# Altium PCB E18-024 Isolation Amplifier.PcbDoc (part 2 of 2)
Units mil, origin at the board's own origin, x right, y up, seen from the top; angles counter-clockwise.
Board outline 5740 x 5970 mil, 4 copper layers (Component Side, V+, V-, Ground), stack 33.234 mil thick; 342 components, 165 nets, 939 pads, 4 vias.
Unrouted connection lines stored in the file: 473.
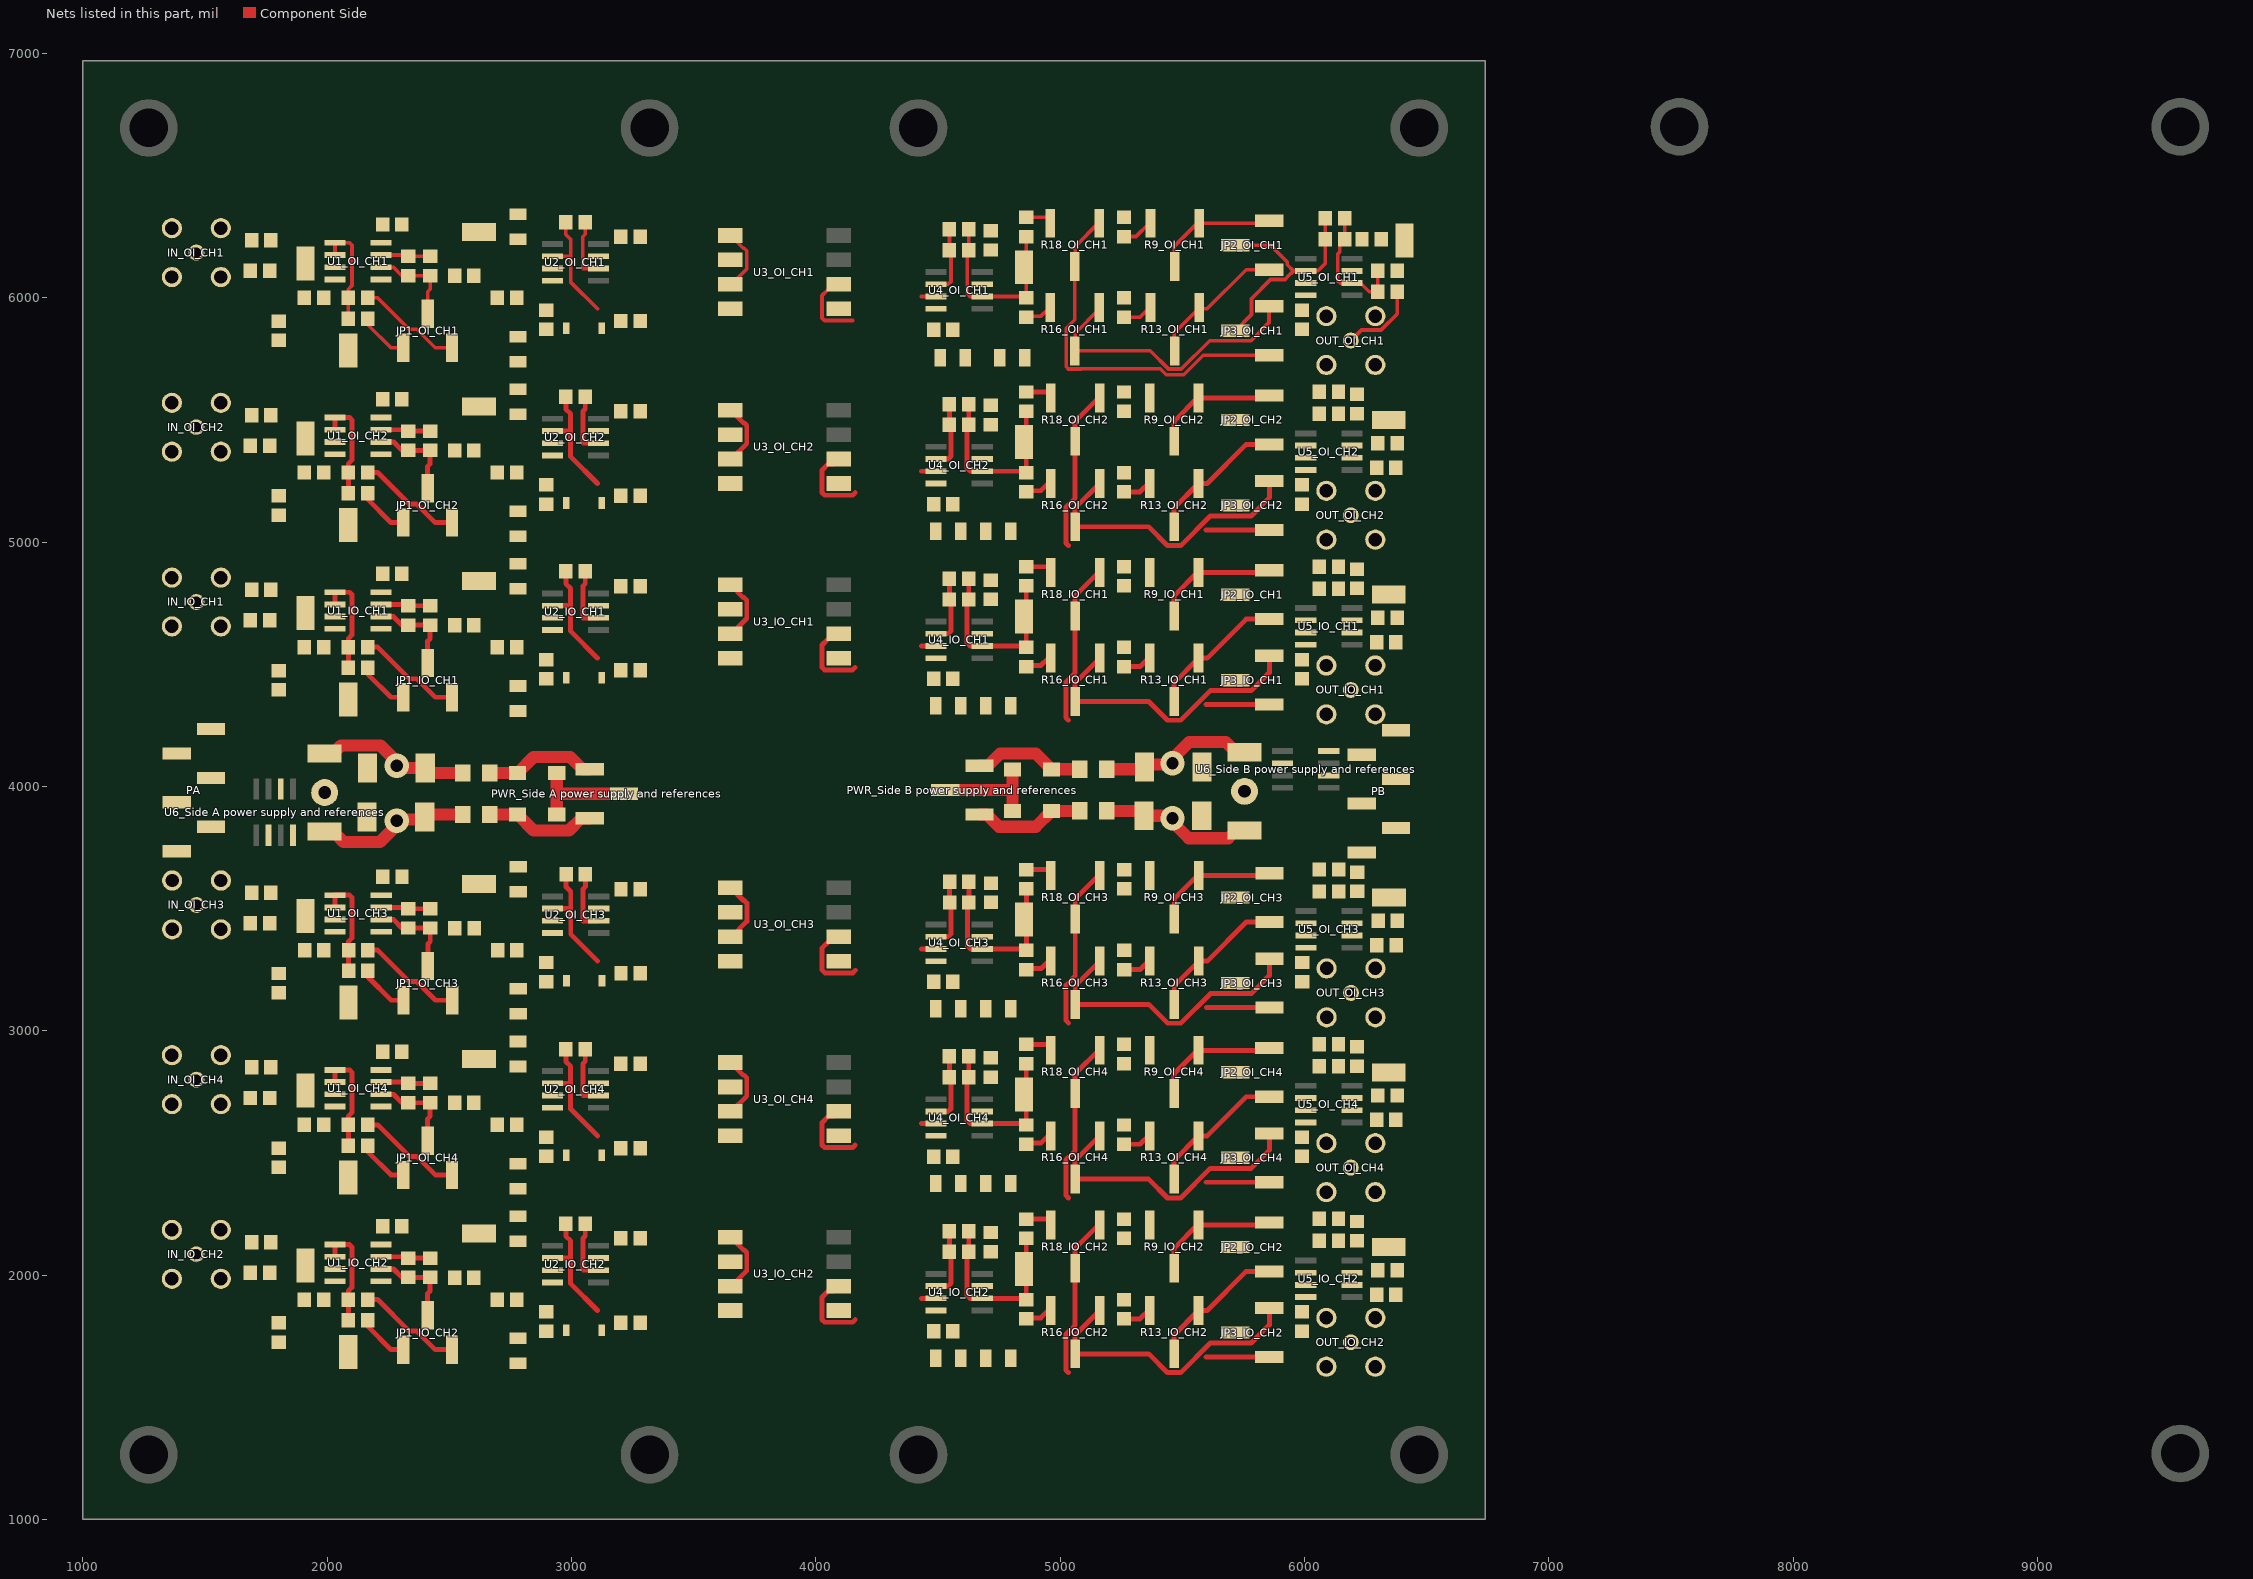
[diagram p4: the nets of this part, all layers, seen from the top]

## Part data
C1_IO_CH1 C1_IO_CH2 C1_OI_CH1 C1_OI_CH2 C1_OI_CH3 C1_OI_CH4 C2_IO_CH1 C2_IO_CH2 C2_OI_CH1 C2_OI_CH2 C2_OI_CH3 C2_OI_CH4 C3_IO_CH1 C3_IO_CH2 C3_OI_CH1 C3_OI_CH2 C3_OI_CH3 C3_OI_CH4 C4_IO_CH1 C4_IO_CH2 C4_OI_CH1 C4_OI_CH2 C4_OI_CH3 C4_OI_CH4 C6_IO_CH1 C6_IO_CH2 C6_OI_CH1 C6_OI_CH2 C6_OI_CH3 C6_OI_CH4 C7_IO_CH1 C7_IO_CH2 C7_OI_CH1 C7_OI_CH2 C7_OI_CH3 C7_OI_CH4 C8_IO_CH1 C8_IO_CH2 C8_OI_CH1 C8_OI_CH2 C8_OI_CH3 C8_OI_CH4 C9_IO_CH1 C9_IO_CH2 C9_OI_CH1 C9_OI_CH2 C9_OI_CH3 C9_OI_CH4 C14_IO_CH1 C14_IO_CH2 C14_OI_CH1 C14_OI_CH2 C14_OI_CH3 C14_OI_CH4 C15_IO_CH1 C15_IO_CH2 C15_OI_CH1 C15_OI_CH2 C15_OI_CH3 C15_OI_CH4 C16_IO_CH1 C16_IO_CH2 C16_OI_CH1 C16_OI_CH2 C16_OI_CH3 C16_OI_CH4 C17_IO_CH1 C17_IO_CH2 C17_OI_CH1 C17_OI_CH2 C17_OI_CH3 C17_OI_CH4: library part Cap, "Capacitor"
C10_IO_CH1 C10_IO_CH2 C10_OI_CH1 C10_OI_CH2 C10_OI_CH3 C10_OI_CH4 C11_IO_CH1 C11_IO_CH2 C11_OI_CH1 C11_OI_CH2 C11_OI_CH3 C11_OI_CH4 C12_IO_CH1 C12_IO_CH2 C12_OI_CH1 C12_OI_CH2 C12_OI_CH3 C12_OI_CH4 C13_IO_CH1 C13_IO_CH2 C13_OI_CH1 C13_OI_CH2 C13_OI_CH3 C13_OI_CH4: library part "Cap Pol3", "CAP TANT POLY 10UF 25V 1206"
"C18_Side A power supply and references" "C18_Side B power supply and references" "C19_Side A power supply and references" "C19_Side B power supply and references": library part "Cap Tant 100uF 10V", Manufacturer=AVX, Part Number=TCJE107M025R0080, Voltage=25V
D1_IO_CH1 D1_IO_CH2 D1_OI_CH1 D1_OI_CH2 D1_OI_CH3 D1_OI_CH4: "High Conductance Fast Diode", Manufacturer="Fairchild Semiconductor"
"D2_Side A power supply and references" "D2_Side B power supply and references" "D3_Side A power supply and references" "D3_Side B power supply and references": "Zener, 18V 1W SMAJ", Manufacturer=MCC, Part Number=SMAZ15-13-F
IN_IO_CH1 IN_IO_CH2 IN_OI_CH1 IN_OI_CH2 IN_OI_CH3 IN_OI_CH4 OUT_IO_CH1 OUT_IO_CH2 OUT_OI_CH1 OUT_OI_CH2 OUT_OI_CH3 OUT_OI_CH4: library part SMB_Male_Vertical, "SMA Male Vertical Mount", Manufacturer=Amphenol
JP1_IO_CH1 JP1_IO_CH2 JP1_OI_CH1 JP1_OI_CH2 JP1_OI_CH3 JP1_OI_CH4 JP2_IO_CH1 JP2_IO_CH2 JP2_OI_CH1 JP2_OI_CH2 JP2_OI_CH3 JP2_OI_CH4 JP3_IO_CH1 JP3_IO_CH2 JP3_OI_CH1 JP3_OI_CH2 JP3_OI_CH3 JP3_OI_CH4 "PWR_Side A power supply and references" "PWR_Side B power supply and references": library part Jumper3p, "3 Pin Jumper Header", Manufacturer="Generic Components"
PA PB: "0.1\" Spacing 1x6 Header", Manufacturer=AMP
R1_IO_CH1 R1_IO_CH2 R1_OI_CH1 R1_OI_CH2 R1_OI_CH3 R1_OI_CH4 R2_IO_CH1 R2_IO_CH2 R2_OI_CH1 R2_OI_CH2 R2_OI_CH3 R2_OI_CH4 R3_IO_CH1 R3_IO_CH2 R3_OI_CH1 R3_OI_CH2 R3_OI_CH3 R3_OI_CH4 R4_IO_CH1 R4_IO_CH2 R4_OI_CH1 R4_OI_CH2 R4_OI_CH3 R4_OI_CH4 R5_IO_CH1 R5_IO_CH2 R5_OI_CH1 R5_OI_CH2 R5_OI_CH3 R5_OI_CH4 R6_IO_CH1 R6_IO_CH2 R6_OI_CH1 R6_OI_CH2 R6_OI_CH3 R6_OI_CH4 R7_IO_CH1 R7_IO_CH2 R7_OI_CH1 R7_OI_CH2 R7_OI_CH3 R7_OI_CH4 R8_IO_CH1 R8_IO_CH2 R8_OI_CH1 R8_OI_CH2 R8_OI_CH3 R8_OI_CH4 R10_IO_CH1 R10_IO_CH2 R10_OI_CH1 R10_OI_CH2 R10_OI_CH3 R10_OI_CH4 R11_IO_CH1 R11_IO_CH2 R11_OI_CH1 R11_OI_CH2 R11_OI_CH3 R11_OI_CH4 R12_IO_CH1 R12_IO_CH2 R12_OI_CH1 R12_OI_CH2 R12_OI_CH3 R12_OI_CH4 R14_IO_CH1 R14_IO_CH2 R14_OI_CH1 R14_OI_CH2 R14_OI_CH3 R14_OI_CH4 R15_IO_CH1 R15_IO_CH2 R15_OI_CH1 R15_OI_CH2 R15_OI_CH3 R15_OI_CH4 R17_IO_CH1 R17_IO_CH2 R17_OI_CH1 R17_OI_CH2 R17_OI_CH3 R17_OI_CH4 R19_IO_CH1 R19_IO_CH2 R19_OI_CH1 R19_OI_CH2 R19_OI_CH3 R19_OI_CH4 R20_IO_CH1 R20_IO_CH2 R20_OI_CH1 R20_OI_CH2 R20_OI_CH3 R20_OI_CH4 R21_IO_CH1 R21_IO_CH2 R21_OI_CH1 R21_OI_CH2 R21_OI_CH3 R21_OI_CH4 "R27_Side A power supply and references" "R27_Side B power supply and references" "R28_Side A power supply and references" "R28_Side B power supply and references": library part Res1, "Resistor"
R9_IO_CH1 R9_IO_CH2 R9_OI_CH1 R9_OI_CH2 R9_OI_CH3 R9_OI_CH4 R13_IO_CH1 R13_IO_CH2 R13_OI_CH1 R13_OI_CH2 R13_OI_CH3 R13_OI_CH4 R16_IO_CH1 R16_IO_CH2 R16_OI_CH1 R16_OI_CH2 R16_OI_CH3 R16_OI_CH4 R18_IO_CH1 R18_IO_CH2 R18_OI_CH1 R18_OI_CH2 R18_OI_CH3 R18_OI_CH4: "SMD POT", Manufacturer=Vishay, Part Number=TS63Y
TP1_IO_CH1 TP1_IO_CH2 TP1_OI_CH1 TP1_OI_CH2 TP1_OI_CH3 TP1_OI_CH4 TP2_IO_CH1 TP2_IO_CH2 TP2_OI_CH1 TP2_OI_CH2 TP2_OI_CH3 TP2_OI_CH4 TP3_IO_CH1 TP3_IO_CH2 TP3_OI_CH1 TP3_OI_CH2 TP3_OI_CH3 TP3_OI_CH4 TP4_IO_CH1 TP4_IO_CH2 TP4_OI_CH1 TP4_OI_CH2 TP4_OI_CH3 TP4_OI_CH4 TP5_IO_CH1 TP5_IO_CH2 TP5_OI_CH1 TP5_OI_CH2 TP5_OI_CH3 TP5_OI_CH4 "TP+_Side A power supply and references" "TP+_Side B power supply and references" "TP-_Side A power supply and references" "TP-_Side B power supply and references" "TPCOM_Side A power supply and references" "TPCOM_Side B power supply and references": library part "TP- Eyelet Terminal", "Eyelet Test Point (white)", Manufacturer=Vero, Part Number=20-313143A
U1_IO_CH1 U1_IO_CH2 U1_OI_CH1 U1_OI_CH2 U1_OI_CH3 U1_OI_CH4 U5_IO_CH1 U5_IO_CH2 U5_OI_CH1 U5_OI_CH2 U5_OI_CH3 U5_OI_CH4: "OVP and EMI Protected, Precision, / Low Noise and Bias Current Dual Op Amp", Manufacturer="Analog Devices"
U2_IO_CH1 U2_IO_CH2 U2_OI_CH1 U2_OI_CH2 U2_OI_CH3 U2_OI_CH4: "36V, 18MHz, Low Noise, JFET Op Amp", Manufacturer="Analog Devices"
U3_IO_CH1 U3_IO_CH2 U3_OI_CH1 U3_OI_CH2 U3_OI_CH3 U3_OI_CH4: "Analog Optocoupler", Manufacturer=Agilent
U4_IO_CH1 U4_IO_CH2 U4_OI_CH1 U4_OI_CH2 U4_OI_CH3 U4_OI_CH4: "36V, 18MHz, Low Noise, JFET Op Amp", Manufacturer="Analog Devices", Part Number=AD548KR
"U6_Side A power supply and references" "U6_Side B power supply and references": "2ppm/°C, Low-Noise, +10V Voltage Reference", Manufacturer=Maxim, Part Number=MAX6325CSA

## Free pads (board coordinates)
  round 236.22 hole 157.48: 5(1270,1265) 5(1270,6695) 5(3320,1265) 5(3320,6695) 5(4420,1265) 5(4420,6695) 5(6470,1265) 5(6470,6695) 5(7535,6700) 5(9585,1270) 5(9585,6700)

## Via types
v1: diameter 100, hole 50, Component Side to Ground, tented both sides, 4 vias

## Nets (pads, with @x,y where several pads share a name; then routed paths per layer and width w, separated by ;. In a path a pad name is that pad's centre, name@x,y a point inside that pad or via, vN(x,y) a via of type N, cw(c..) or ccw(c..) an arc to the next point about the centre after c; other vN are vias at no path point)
+10REFA: "U6_Side A power supply and references.6" R1_IO_CH1.2 R1_IO_CH2.2 R8_OI_CH1.2 R8_OI_CH2.2 R8_OI_CH3.2 R8_OI_CH4.2 R11_OI_CH1.2 R11_OI_CH2.2 R11_OI_CH3.2 R11_OI_CH4.2
+10REFB: "U6_Side B power supply and references.6" R1_OI_CH1.2 R1_OI_CH2.2 R1_OI_CH3.2 R1_OI_CH4.2 R8_IO_CH1.2 R8_IO_CH2.2 R11_IO_CH1.2 R11_IO_CH2.2
+15A: "C18_Side A power supply and references.1" "R27_Side A power supply and references.1" "TP+_Side A power supply and references.1" "U6_Side A power supply and references.2" C6_IO_CH1.2 C6_IO_CH2.2 C7_IO_CH1.2 C7_IO_CH2.2 C8_OI_CH1.2 C8_OI_CH2.2 C8_OI_CH3.2 C8_OI_CH4.2 C9_OI_CH1.2 C9_OI_CH2.2 C9_OI_CH3.2 C9_OI_CH4.2 C10_IO_CH1.1 C10_IO_CH2.1 C11_OI_CH1.1 C11_OI_CH2.1 C11_OI_CH3.1 C11_OI_CH4.1 U1_IO_CH1.8 U1_IO_CH2.8 U2_IO_CH1.7 U2_IO_CH2.7 U4_OI_CH1.7 U4_OI_CH2.7 U4_OI_CH3.7 U4_OI_CH4.7 U5_OI_CH1.7 U5_OI_CH2.7 U5_OI_CH3.7 U5_OI_CH4.7 | length 609.6
  Component Side w20: 1960,3815 1990,3815
  Component Side w50: 2035,3805 2067.06,3772.94 2216.82,3772.94 2308.87,3865 2400,3865 2420,3885 2554.88,3885
  other v1: 2285,3860
+15B: "C18_Side B power supply and references.1" "R27_Side B power supply and references.1" "TP+_Side B power supply and references.1" "U6_Side B power supply and references.2" C6_OI_CH1.2 C6_OI_CH2.2 C6_OI_CH3.2 C6_OI_CH4.2 C7_OI_CH1.2 C7_OI_CH2.2 C7_OI_CH3.2 C7_OI_CH4.2 C8_IO_CH2.2 C9_IO_CH2.2 C10_OI_CH1.1 C10_OI_CH2.1 C10_OI_CH3.1 C10_OI_CH4.1 C11_IO_CH2.1 U1_OI_CH1.8 U1_OI_CH2.8 U1_OI_CH3.8 U1_OI_CH4.8 U2_OI_CH1.7 U2_OI_CH2.7 U2_OI_CH3.7 U2_OI_CH4.7 U4_IO_CH2.7 U5_IO_CH2.7 | length 609.6
  Component Side w20: 5755,4140 5785,4140
  Component Side w50: 5190.12,4070 5325,4070 5345,4090 5436.13,4090 5528.18,4182.06 5677.94,4182.06 5710,4150
  other v1: 5460,4095
"+Vin_Side A power supply and references": "D2_Side A power supply and references.2" "PWR_Side A power supply and references.1" "R27_Side A power supply and references.2" | length 457.6
  Component Side w50: 2665,3885 2665.12,3885 2780,3885 2845,3820 2990,3820 3040,3870 3075,3870
"+Vin_Side B power supply and references": "D2_Side B power supply and references.2" "PWR_Side B power supply and references.1" "R27_Side B power supply and references.2" | length 457.6
  Component Side w50: 4670,4085 4705,4085 4755,4135 4900,4135 4965,4070 5079.88,4070 5080,4070
-15A: "C19_Side A power supply and references.2" "R28_Side A power supply and references.1" "TP-_Side A power supply and references.1" C12_IO_CH1.2 C12_IO_CH2.2 C13_OI_CH1.2 C13_OI_CH2.2 C13_OI_CH3.2 C13_OI_CH4.2 C14_IO_CH1.2 C14_IO_CH2.2 C15_IO_CH1.2 C15_IO_CH2.2 C16_OI_CH1.2 C16_OI_CH2.2 C16_OI_CH3.2 C16_OI_CH4.2 C17_OI_CH1.2 C17_OI_CH2.2 C17_OI_CH3.2 C17_OI_CH4.2 U1_IO_CH1.4 U1_IO_CH2.4 U2_IO_CH1.4 U2_IO_CH2.4 U4_OI_CH1.4 U4_OI_CH2.4 U4_OI_CH3.4 U4_OI_CH4.4 U5_OI_CH1.4 U5_OI_CH2.4 U5_OI_CH3.4 U5_OI_CH4.4 | length 592.9
  Component Side w50: 2025,4135 2057.06,4167.06 2218.04,4167.06 2310.09,4075 2401.22,4075 ; 2400,4080 2425,4055 2554.88,4055
  other v1: 2285,4085
-15B: "C19_Side B power supply and references.2" "R28_Side B power supply and references.1" "TP-_Side B power supply and references.1" C12_OI_CH1.2 C12_OI_CH2.2 C12_OI_CH3.2 C12_OI_CH4.2 C13_IO_CH2.2 C14_OI_CH1.2 C14_OI_CH2.2 C14_OI_CH3.2 C14_OI_CH4.2 C15_OI_CH1.2 C15_OI_CH2.2 C15_OI_CH3.2 C15_OI_CH4.2 C16_IO_CH2.2 C17_IO_CH2.2 U1_OI_CH1.4 U1_OI_CH2.4 U1_OI_CH3.4 U1_OI_CH4.4 U2_OI_CH1.4 U2_OI_CH2.4 U2_OI_CH3.4 U2_OI_CH4.4 U4_IO_CH2.4 U5_IO_CH2.4 | length 592.9
  Component Side w50: 5190.12,3900 5320,3900 5345,3875 ; 5343.78,3880 5434.91,3880 5526.96,3787.94 5687.94,3787.94 5720,3820
  other v1: 5460,3870
"-Vin_Side A power supply and references": "D3_Side A power supply and references.1" "PWR_Side A power supply and references.3" "R28_Side A power supply and references.2" | length 457.6
  Component Side w50: 2665,4055 2665.12,4055 2780,4055 2845,4120 2995,4120 3045,4070 3075,4070
"-Vin_Side B power supply and references": "D3_Side B power supply and references.1" "PWR_Side B power supply and references.3" "R28_Side B power supply and references.2" | length 457.6
  Component Side w50: 4670,3885 4700,3885 4750,3835 4900,3835 4965,3900 5079.88,3900 5080,3900
COMA: "C18_Side A power supply and references.2" "C19_Side A power supply and references.1" "D2_Side A power supply and references.1" "D3_Side A power supply and references.2" "PWR_Side A power supply and references.2" "TPCOM_Side A power supply and references.1" "U6_Side A power supply and references.4" C6_IO_CH1.1 C6_IO_CH2.1 C7_IO_CH1.1 C7_IO_CH2.1 C8_OI_CH1.1 C8_OI_CH2.1 C8_OI_CH3.1 C8_OI_CH4.1 C9_OI_CH1.1 C9_OI_CH2.1 C9_OI_CH3.1 C9_OI_CH4.1 C10_IO_CH1.2 C10_IO_CH2.2 C11_OI_CH1.2 C11_OI_CH2.2 C11_OI_CH3.2 C11_OI_CH4.2 C12_IO_CH1.1 C12_IO_CH2.1 C13_OI_CH1.1 C13_OI_CH2.1 C13_OI_CH3.1 C13_OI_CH4.1 C14_IO_CH1.1 C14_IO_CH2.1 C15_IO_CH1.1 C15_IO_CH2.1 C16_OI_CH1.1 C16_OI_CH2.1 C16_OI_CH3.1 C16_OI_CH4.1 C17_OI_CH1.1 C17_OI_CH2.1 C17_OI_CH3.1 C17_OI_CH4.1 D1_IO_CH1.1 D1_IO_CH2.1 IN_IO_CH1.2 IN_IO_CH2.2 OUT_OI_CH1.2 OUT_OI_CH2.2 OUT_OI_CH3.2 OUT_OI_CH4.2 R7_IO_CH1.1 R7_IO_CH2.1 U1_IO_CH1.5 U1_IO_CH2.5 U2_IO_CH1.3 U2_IO_CH2.3 U3_IO_CH1.1 U3_IO_CH1.3 U3_IO_CH2.1 U3_IO_CH2.3 U3_OI_CH1.6 U3_OI_CH2.6 U3_OI_CH3.6 U3_OI_CH4.6 U4_OI_CH1.3 U4_OI_CH2.3 U4_OI_CH3.3 U4_OI_CH4.3 U5_OI_CH1.3 U5_OI_CH2.3 U5_OI_CH3.3 U5_OI_CH4.3 | length 2484.5
  Component Side w15: U3_OI_CH1.6@4093.54,6055 4073.54,6035 4051.54,6035 4025.54,6009 4025.54,5917.54 4036.08,5907 4150.99,5907 ; 4431.54,6005 U4_OI_CH1.3@4491.54,6005
  Component Side w20: U3_IO_CH2.3@3649.54,1955 3654.99,1955 3717.54,2017.54 3717.54,2092.46 3706.99,2103 3703.54,2103 U3_IO_CH2.1@3651.54,2155 ; U3_IO_CH1.3@3649.54,4625 3654.99,4625 3717.54,4687.54 3717.54,4762.46 3706.99,4773 3703.54,4773 U3_IO_CH1.1@3651.54,4825 ; U3_OI_CH4.6@4093.54,2670 4073.54,2650 4051.54,2650 4025.54,2624 4025.54,2532.54 4036.08,2522 4150.99,2522 4161.54,2532.54 ; U3_OI_CH2.6@4093.54,5340 4073.54,5320 4051.54,5320 4025.54,5294 4025.54,5202.54 4036.08,5192 4150.99,5192 4161.54,5202.54 ; U3_OI_CH3.6@4094.17,3385 4074.17,3365 4052.17,3365 4026.17,3339 4026.17,3247.54 4036.71,3237 4151.62,3237 4162.17,3247.54 ; 4431.54,2620 U4_OI_CH4.3@4491.54,2620 ; 4431.54,5290 U4_OI_CH2.3@4491.54,5290 ; 4432.17,3335 U4_OI_CH3.3@4492.17,3335
  Component Side w50: 2940,3885 2940,3970 ; 2940,4055 2940,3970 ; 3215,3970 2940,3970
COMB: "C18_Side B power supply and references.2" "C19_Side B power supply and references.1" "D2_Side B power supply and references.1" "D3_Side B power supply and references.2" "PWR_Side B power supply and references.2" "TPCOM_Side B power supply and references.1" "U6_Side B power supply and references.4" C6_OI_CH1.1 C6_OI_CH2.1 C6_OI_CH3.1 C6_OI_CH4.1 C7_OI_CH1.1 C7_OI_CH2.1 C7_OI_CH3.1 C7_OI_CH4.1 C8_IO_CH2.1 C9_IO_CH2.1 C10_OI_CH1.2 C10_OI_CH2.2 C10_OI_CH3.2 C10_OI_CH4.2 C11_IO_CH2.2 C12_OI_CH1.1 C12_OI_CH2.1 C12_OI_CH3.1 C12_OI_CH4.1 C13_IO_CH2.1 C14_OI_CH1.1 C14_OI_CH2.1 C14_OI_CH3.1 C14_OI_CH4.1 C15_OI_CH1.1 C15_OI_CH2.1 C15_OI_CH3.1 C15_OI_CH4.1 C16_IO_CH2.1 C17_IO_CH2.1 D1_OI_CH1.1 D1_OI_CH2.1 D1_OI_CH3.1 D1_OI_CH4.1 IN_OI_CH1.2 IN_OI_CH2.2 IN_OI_CH3.2 IN_OI_CH4.2 OUT_IO_CH2.2 R7_OI_CH1.1 R7_OI_CH2.1 R7_OI_CH3.1 R7_OI_CH4.1 U1_OI_CH1.5 U1_OI_CH2.5 U1_OI_CH3.5 U1_OI_CH4.5 U2_OI_CH1.3 U2_OI_CH2.3 U2_OI_CH3.3 U2_OI_CH4.3 U3_IO_CH2.6 U3_OI_CH1.1 U3_OI_CH1.3 U3_OI_CH2.1 U3_OI_CH2.3 U3_OI_CH3.1 U3_OI_CH3.3 U3_OI_CH4.1 U3_OI_CH4.3 U4_IO_CH2.3 U5_IO_CH2.3 | length 1871.1
  Component Side w15: U3_OI_CH1.3@3649.54,6055 3654.99,6055 3717.54,6117.54 3717.54,6192.46 3706.99,6203 3703.54,6203 U3_OI_CH1.1@3651.54,6255
  Component Side w20: U3_OI_CH4.3@3649.54,2670 3654.99,2670 3717.54,2732.54 3717.54,2807.46 3706.99,2818 3703.54,2818 U3_OI_CH4.1@3651.54,2870 ; U3_OI_CH2.3@3649.54,5340 3654.99,5340 3717.54,5402.54 3717.54,5477.46 3706.99,5488 3703.54,5488 U3_OI_CH2.1@3651.54,5540 ; U3_OI_CH3.3@3650.17,3385 3655.62,3385 3718.17,3447.54 3718.17,3522.46 3707.62,3533 3704.17,3533 U3_OI_CH3.1@3652.17,3585 ; U3_IO_CH2.6@4093.54,1955 4073.54,1935 4051.54,1935 4025.54,1909 4025.54,1817.54 4036.08,1807 4150.99,1807 4161.54,1817.54 ; 4431.54,1905 U4_IO_CH2.3@4491.54,1905
  Component Side w50: 4530,3985 4805,3985 ; 4805,3900 4805,3985 ; 4805,4070 4805,3985
COMOUT_IO_CH1: C8_IO_CH1.1 C9_IO_CH1.1 C11_IO_CH1.2 C13_IO_CH1.1 C16_IO_CH1.1 C17_IO_CH1.1 OUT_IO_CH1.2 U3_IO_CH1.6 U4_IO_CH1.3 U5_IO_CH1.3 | length 383.2
  Component Side w20: U3_IO_CH1.6@4093.54,4625 4073.54,4605 4051.54,4605 4025.54,4579 4025.54,4487.54 4036.08,4477 4150.99,4477 4161.54,4487.54 ; 4431.54,4575 U4_IO_CH1.3@4491.54,4575
NetC1_IO_CH1_1: C1_IO_CH1.1 R2_IO_CH1.1 R4_IO_CH1.1 TP3_IO_CH1.1 U1_IO_CH1.7 | length 207.8
  Component Side w20: U1_IO_CH1.7@2221.02,4745 2331.54,4745 R2_IO_CH1.1@2336.54,4740 ; R2_IO_CH1.1@2331.54,4740 R2_IO_CH1.1@2332.17,4739.37 C1_IO_CH1.1@2421.54,4739.37
NetC1_IO_CH1_2: C1_IO_CH1.2 JP1_IO_CH1.2 R1_IO_CH1.1 R2_IO_CH1.2 U1_IO_CH1.6 | length 368.6
  Component Side w20: U1_IO_CH1.6@2226.54,4695 2271.54,4695 2305.91,4660.63 R2_IO_CH1.2@2332.17,4660.63 2420.91,4660.63 2421.54,4660 2421.54,4605 2411.54,4595 JP1_IO_CH1.2@2411.54,4505
NetC1_IO_CH2_1: C1_IO_CH2.1 R2_IO_CH2.1 R4_IO_CH2.1 TP3_IO_CH2.1 U1_IO_CH2.7 | length 207.8
  Component Side w20: U1_IO_CH2.7@2221.02,2075 2331.54,2075 R2_IO_CH2.1@2336.54,2070 ; R2_IO_CH2.1@2331.54,2070 R2_IO_CH2.1@2332.17,2069.37 C1_IO_CH2.1@2421.54,2069.37
NetC1_IO_CH2_2: C1_IO_CH2.2 JP1_IO_CH2.2 R1_IO_CH2.1 R2_IO_CH2.2 U1_IO_CH2.6 | length 368.6
  Component Side w20: U1_IO_CH2.6@2226.54,2025 2271.54,2025 2305.91,1990.63 R2_IO_CH2.2@2332.17,1990.63 2420.91,1990.63 2421.54,1990 2421.54,1935 2411.54,1925 JP1_IO_CH2.2@2411.54,1835
NetC1_OI_CH1_1: C1_OI_CH1.1 R2_OI_CH1.1 R4_OI_CH1.1 TP3_OI_CH1.1 U1_OI_CH1.7 | length 207.8
  Component Side w15: U1_OI_CH1.7@2221.02,6175 2331.54,6175 R2_OI_CH1.1@2336.54,6170 ; R2_OI_CH1.1@2331.54,6170 R2_OI_CH1.1@2332.17,6169.37 C1_OI_CH1.1@2421.54,6169.37
NetC1_OI_CH1_2: C1_OI_CH1.2 JP1_OI_CH1.2 R1_OI_CH1.1 R2_OI_CH1.2 U1_OI_CH1.6 | length 368.6
  Component Side w15: U1_OI_CH1.6@2226.54,6125 2271.54,6125 2305.91,6090.63 R2_OI_CH1.2@2332.17,6090.63 2420.91,6090.63 2421.54,6090 2421.54,6035 2411.54,6025 JP1_OI_CH1.2@2411.54,5935
NetC1_OI_CH2_1: C1_OI_CH2.1 R2_OI_CH2.1 R4_OI_CH2.1 TP3_OI_CH2.1 U1_OI_CH2.7 | length 207.8
  Component Side w20: U1_OI_CH2.7@2221.02,5460 2331.54,5460 R2_OI_CH2.1@2336.54,5455 ; R2_OI_CH2.1@2331.54,5455 R2_OI_CH2.1@2332.17,5454.37 C1_OI_CH2.1@2421.54,5454.37
NetC1_OI_CH2_2: C1_OI_CH2.2 JP1_OI_CH2.2 R1_OI_CH2.1 R2_OI_CH2.2 U1_OI_CH2.6 | length 368.6
  Component Side w20: U1_OI_CH2.6@2226.54,5410 2271.54,5410 2305.91,5375.63 R2_OI_CH2.2@2332.17,5375.63 2420.91,5375.63 2421.54,5375 2421.54,5320 2411.54,5310 JP1_OI_CH2.2@2411.54,5220
NetC1_OI_CH3_1: C1_OI_CH3.1 R2_OI_CH3.1 R4_OI_CH3.1 TP3_OI_CH3.1 U1_OI_CH3.7 | length 207.8
  Component Side w20: U1_OI_CH3.7@2221.65,3505 2332.17,3505 R2_OI_CH3.1@2337.17,3500 ; R2_OI_CH3.1@2332.17,3500 R2_OI_CH3.1@2332.8,3499.37 C1_OI_CH3.1@2422.17,3499.37
NetC1_OI_CH3_2: C1_OI_CH3.2 JP1_OI_CH3.2 R1_OI_CH3.1 R2_OI_CH3.2 U1_OI_CH3.6 | length 368.6
  Component Side w20: U1_OI_CH3.6@2227.17,3455 2272.17,3455 2306.54,3420.63 R2_OI_CH3.2@2332.8,3420.63 2421.54,3420.63 2422.17,3420 2422.17,3365 2412.17,3355 JP1_OI_CH3.2@2412.17,3265
NetC1_OI_CH4_1: C1_OI_CH4.1 R2_OI_CH4.1 R4_OI_CH4.1 TP3_OI_CH4.1 U1_OI_CH4.7 | length 207.8
  Component Side w20: U1_OI_CH4.7@2221.02,2790 2331.54,2790 R2_OI_CH4.1@2336.54,2785 ; R2_OI_CH4.1@2331.54,2785 R2_OI_CH4.1@2332.17,2784.37 C1_OI_CH4.1@2421.54,2784.37
NetC1_OI_CH4_2: C1_OI_CH4.2 JP1_OI_CH4.2 R1_OI_CH4.1 R2_OI_CH4.2 U1_OI_CH4.6 | length 368.6
  Component Side w20: U1_OI_CH4.6@2226.54,2740 2271.54,2740 2305.91,2705.63 R2_OI_CH4.2@2332.17,2705.63 2420.91,2705.63 2421.54,2705 2421.54,2650 2411.54,2640 JP1_OI_CH4.2@2411.54,2550
NetC2_IO_CH1_1: C2_IO_CH1.1 R5_IO_CH1.1 U2_IO_CH1.6 | length 248.6
  Component Side w20: C2_IO_CH1.1@3056.54,4870 3056.54,4830 3046.54,4820 3046.54,4690 U2_IO_CH1.6@3111.02,4690
NetC2_IO_CH1_2: C2_IO_CH1.2 R4_IO_CH1.2 U2_IO_CH1.2 U3_IO_CH1.4 | length 475.6
  Component Side w20: U2_IO_CH1.2@2921.54,4740 U2_IO_CH1.2@2922.05,4740 2996.54,4740 ; C2_IO_CH1.2@2977.17,4870 2977.17,4829.37 2996.54,4810 2996.54,4740 ; 3106.54,4525 2996.54,4635 2996.54,4740 ; U3_IO_CH1.4@3649.54,4525 U3_IO_CH1.4@3651.54,4525
NetC2_IO_CH2_1: C2_IO_CH2.1 R5_IO_CH2.1 U2_IO_CH2.6 | length 248.6
  Component Side w20: C2_IO_CH2.1@3056.54,2200 3056.54,2160 3046.54,2150 3046.54,2020 U2_IO_CH2.6@3111.02,2020
NetC2_IO_CH2_2: C2_IO_CH2.2 R4_IO_CH2.2 U2_IO_CH2.2 U3_IO_CH2.4 | length 475.6
  Component Side w20: U2_IO_CH2.2@2921.54,2070 U2_IO_CH2.2@2922.05,2070 2996.54,2070 ; C2_IO_CH2.2@2977.17,2200 2977.17,2159.37 2996.54,2140 2996.54,2070 ; 3106.54,1855 2996.54,1965 2996.54,2070 ; U3_IO_CH2.4@3649.54,1855 U3_IO_CH2.4@3651.54,1855
NetC2_OI_CH1_1: C2_OI_CH1.1 R5_OI_CH1.1 U2_OI_CH1.6 | length 248.6
  Component Side w15: C2_OI_CH1.1@3056.54,6300 3056.54,6260 3046.54,6250 3046.54,6120 U2_OI_CH1.6@3111.02,6120
NetC2_OI_CH1_2: C2_OI_CH1.2 R4_OI_CH1.2 U2_OI_CH1.2 U3_OI_CH1.4 | length 475.6
  Component Side w15: U2_OI_CH1.2@2921.54,6170 U2_OI_CH1.2@2922.05,6170 2996.54,6170 ; C2_OI_CH1.2@2977.17,6300 2977.17,6259.37 2996.54,6240 2996.54,6170 ; 3106.54,5955 2996.54,6065 2996.54,6170 ; U3_OI_CH1.4@3649.54,5955 U3_OI_CH1.4@3651.54,5955
NetC2_OI_CH2_1: C2_OI_CH2.1 R5_OI_CH2.1 U2_OI_CH2.6 | length 248.6
  Component Side w20: C2_OI_CH2.1@3056.54,5585 3056.54,5545 3046.54,5535 3046.54,5405 U2_OI_CH2.6@3111.02,5405
NetC2_OI_CH2_2: C2_OI_CH2.2 R4_OI_CH2.2 U2_OI_CH2.2 U3_OI_CH2.4 | length 475.6
  Component Side w20: U2_OI_CH2.2@2921.54,5455 U2_OI_CH2.2@2922.05,5455 2996.54,5455 ; C2_OI_CH2.2@2977.17,5585 2977.17,5544.37 2996.54,5525 2996.54,5455 ; 3106.54,5240 2996.54,5350 2996.54,5455 ; U3_OI_CH2.4@3649.54,5240 U3_OI_CH2.4@3651.54,5240
NetC2_OI_CH3_1: C2_OI_CH3.1 R5_OI_CH3.1 U2_OI_CH3.6 | length 248.6
  Component Side w20: C2_OI_CH3.1@3057.17,3630 3057.17,3590 3047.17,3580 3047.17,3450 U2_OI_CH3.6@3111.65,3450
NetC2_OI_CH3_2: C2_OI_CH3.2 R4_OI_CH3.2 U2_OI_CH3.2 U3_OI_CH3.4 | length 475.6
  Component Side w20: U2_OI_CH3.2@2922.17,3500 U2_OI_CH3.2@2922.68,3500 2997.17,3500 ; C2_OI_CH3.2@2977.8,3630 2977.8,3589.37 2997.17,3570 2997.17,3500 ; 3107.17,3285 2997.17,3395 2997.17,3500 ; U3_OI_CH3.4@3650.17,3285 U3_OI_CH3.4@3652.17,3285
NetC2_OI_CH4_1: C2_OI_CH4.1 R5_OI_CH4.1 U2_OI_CH4.6 | length 248.6
  Component Side w20: C2_OI_CH4.1@3056.54,2915 3056.54,2875 3046.54,2865 3046.54,2735 U2_OI_CH4.6@3111.02,2735
NetC2_OI_CH4_2: C2_OI_CH4.2 R4_OI_CH4.2 U2_OI_CH4.2 U3_OI_CH4.4 | length 475.6
  Component Side w20: U2_OI_CH4.2@2921.54,2785 U2_OI_CH4.2@2922.05,2785 2996.54,2785 ; C2_OI_CH4.2@2977.17,2915 2977.17,2874.37 2996.54,2855 2996.54,2785 ; 3106.54,2570 2996.54,2680 2996.54,2785 ; U3_OI_CH4.4@3649.54,2570 U3_OI_CH4.4@3651.54,2570
NetC3_IO_CH1_1: C3_IO_CH1.1 R10_IO_CH1.2 R14_IO_CH1.2 R17_IO_CH1.2 TP4_IO_CH1.1 U4_IO_CH1.6 | length 819.3
  Component Side w20: R10_IO_CH1.2@4625.91,4765 4619.72,4758.81 4619.72,4586.82 4631.54,4575 U4_IO_CH1.6@4681.02,4575 ; C3_IO_CH1.1@4625.91,4850 4625.91,4765.63 R10_IO_CH1.2@4626.54,4765 ; 4636.02,4575 4856.54,4575 R14_IO_CH1.2@4861.54,4570 ; R14_IO_CH1.2@4861.54,4569.37 4861.54,4685 TP4_IO_CH1.1@4851.54,4695 4861.54,4705 R17_IO_CH1.2@4861.54,4820.63
NetC3_IO_CH1_2: C3_IO_CH1.2 R10_IO_CH1.1 U3_IO_CH1.5 U4_IO_CH1.2 | length 289.7
  Component Side w20: U3_IO_CH1.5@4091.54,4525 U3_IO_CH1.5@4093.54,4525 U3_IO_CH1.5@4098.99,4525 ; U4_IO_CH1.2@4492.05,4625 4541.54,4625 4553.36,4636.82 4553.36,4758.81 R10_IO_CH1.1@4547.17,4765 ; R10_IO_CH1.1@4546.54,4765 4547.17,4765.63 C3_IO_CH1.2@4547.17,4850
NetC3_IO_CH2_1: C3_IO_CH2.1 R10_IO_CH2.2 R14_IO_CH2.2 R17_IO_CH2.2 TP4_IO_CH2.1 U4_IO_CH2.6 | length 819.3
  Component Side w20: R10_IO_CH2.2@4625.91,2095 4619.72,2088.81 4619.72,1916.82 4631.54,1905 U4_IO_CH2.6@4681.02,1905 ; C3_IO_CH2.1@4625.91,2180 4625.91,2095.63 R10_IO_CH2.2@4626.54,2095 ; 4636.02,1905 4856.54,1905 R14_IO_CH2.2@4861.54,1900 ; R14_IO_CH2.2@4861.54,1899.37 4861.54,2015 TP4_IO_CH2.1@4851.54,2025 4861.54,2035 R17_IO_CH2.2@4861.54,2150.63
NetC3_IO_CH2_2: C3_IO_CH2.2 R10_IO_CH2.1 U3_IO_CH2.5 U4_IO_CH2.2 | length 289.7
  Component Side w20: U3_IO_CH2.5@4091.54,1855 U3_IO_CH2.5@4093.54,1855 U3_IO_CH2.5@4098.99,1855 ; U4_IO_CH2.2@4492.05,1955 4541.54,1955 4553.36,1966.82 4553.36,2088.81 R10_IO_CH2.1@4547.17,2095 ; R10_IO_CH2.1@4546.54,2095 4547.17,2095.63 C3_IO_CH2.2@4547.17,2180
NetC3_OI_CH1_1: C3_OI_CH1.1 R10_OI_CH1.2 R14_OI_CH1.2 R17_OI_CH1.2 TP4_OI_CH1.1 U4_OI_CH1.6 | length 819.3
  Component Side w15: R10_OI_CH1.2@4625.91,6195 4619.72,6188.81 4619.72,6016.82 4631.54,6005 U4_OI_CH1.6@4681.02,6005 ; C3_OI_CH1.1@4625.91,6280 4625.91,6195.63 R10_OI_CH1.2@4626.54,6195 ; 4636.02,6005 4856.54,6005 R14_OI_CH1.2@4861.54,6000 ; R14_OI_CH1.2@4861.54,5999.37 4861.54,6115 TP4_OI_CH1.1@4851.54,6125 4861.54,6135 R17_OI_CH1.2@4861.54,6250.63
NetC3_OI_CH1_2: C3_OI_CH1.2 R10_OI_CH1.1 U3_OI_CH1.5 U4_OI_CH1.2 | length 289.7
  Component Side w15: U3_OI_CH1.5@4091.54,5955 U3_OI_CH1.5@4093.54,5955 U3_OI_CH1.5@4098.99,5955 ; U4_OI_CH1.2@4492.05,6055 4541.54,6055 4553.36,6066.82 4553.36,6188.81 R10_OI_CH1.1@4547.17,6195 ; R10_OI_CH1.1@4546.54,6195 4547.17,6195.63 C3_OI_CH1.2@4547.17,6280
NetC3_OI_CH2_1: C3_OI_CH2.1 R10_OI_CH2.2 R14_OI_CH2.2 R17_OI_CH2.2 TP4_OI_CH2.1 U4_OI_CH2.6 | length 819.3
  Component Side w20: R10_OI_CH2.2@4625.91,5480 4619.72,5473.81 4619.72,5301.82 4631.54,5290 U4_OI_CH2.6@4681.02,5290 ; C3_OI_CH2.1@4625.91,5565 4625.91,5480.63 R10_OI_CH2.2@4626.54,5480 ; 4636.02,5290 4856.54,5290 R14_OI_CH2.2@4861.54,5285 ; R14_OI_CH2.2@4861.54,5284.37 4861.54,5400 TP4_OI_CH2.1@4851.54,5410 4861.54,5420 R17_OI_CH2.2@4861.54,5535.63
NetC3_OI_CH2_2: C3_OI_CH2.2 R10_OI_CH2.1 U3_OI_CH2.5 U4_OI_CH2.2 | length 289.7
  Component Side w20: U3_OI_CH2.5@4091.54,5240 U3_OI_CH2.5@4093.54,5240 U3_OI_CH2.5@4098.99,5240 ; U4_OI_CH2.2@4492.05,5340 4541.54,5340 4553.36,5351.82 4553.36,5473.81 R10_OI_CH2.1@4547.17,5480 ; R10_OI_CH2.1@4546.54,5480 4547.17,5480.63 C3_OI_CH2.2@4547.17,5565
NetC3_OI_CH3_1: C3_OI_CH3.1 R10_OI_CH3.2 R14_OI_CH3.2 R17_OI_CH3.2 TP4_OI_CH3.1 U4_OI_CH3.6 | length 819.3
  Component Side w20: R10_OI_CH3.2@4626.54,3525 4620.35,3518.81 4620.35,3346.82 4632.17,3335 U4_OI_CH3.6@4681.65,3335 ; C3_OI_CH3.1@4626.54,3610 4626.54,3525.63 R10_OI_CH3.2@4627.17,3525 ; 4636.65,3335 4857.17,3335 R14_OI_CH3.2@4862.17,3330 ; R14_OI_CH3.2@4862.17,3329.37 4862.17,3445 TP4_OI_CH3.1@4852.17,3455 4862.17,3465 R17_OI_CH3.2@4862.17,3580.63
NetC3_OI_CH3_2: C3_OI_CH3.2 R10_OI_CH3.1 U3_OI_CH3.5 U4_OI_CH3.2 | length 289.7
  Component Side w20: U3_OI_CH3.5@4092.17,3285 U3_OI_CH3.5@4094.17,3285 U3_OI_CH3.5@4099.62,3285 ; U4_OI_CH3.2@4492.68,3385 4542.17,3385 4553.99,3396.82 4553.99,3518.81 R10_OI_CH3.1@4547.8,3525 ; R10_OI_CH3.1@4547.17,3525 4547.8,3525.63 C3_OI_CH3.2@4547.8,3610
NetC3_OI_CH4_1: C3_OI_CH4.1 R10_OI_CH4.2 R14_OI_CH4.2 R17_OI_CH4.2 TP4_OI_CH4.1 U4_OI_CH4.6 | length 819.3
  Component Side w20: R10_OI_CH4.2@4625.91,2810 4619.72,2803.81 4619.72,2631.82 4631.54,2620 U4_OI_CH4.6@4681.02,2620 ; C3_OI_CH4.1@4625.91,2895 4625.91,2810.63 R10_OI_CH4.2@4626.54,2810 ; 4636.02,2620 4856.54,2620 R14_OI_CH4.2@4861.54,2615 ; R14_OI_CH4.2@4861.54,2614.37 4861.54,2730 TP4_OI_CH4.1@4851.54,2740 4861.54,2750 R17_OI_CH4.2@4861.54,2865.63
NetC3_OI_CH4_2: C3_OI_CH4.2 R10_OI_CH4.1 U3_OI_CH4.5 U4_OI_CH4.2 | length 289.7
  Component Side w20: U3_OI_CH4.5@4091.54,2570 U3_OI_CH4.5@4093.54,2570 U3_OI_CH4.5@4098.99,2570 ; U4_OI_CH4.2@4492.05,2670 4541.54,2670 4553.36,2681.82 4553.36,2803.81 R10_OI_CH4.1@4547.17,2810 ; R10_OI_CH4.1@4546.54,2810 4547.17,2810.63 C3_OI_CH4.2@4547.17,2895
NetC4_IO_CH1_1: C4_IO_CH1.1 R12_IO_CH1.1 R15_IO_CH1.2 R21_IO_CH1.2 TP5_IO_CH1.1 U5_IO_CH1.6
NetC4_IO_CH1_2: C4_IO_CH1.2 JP2_IO_CH1.2 JP3_IO_CH1.2 R12_IO_CH1.2 U5_IO_CH1.2
NetC4_IO_CH2_1: C4_IO_CH2.1 R12_IO_CH2.1 R15_IO_CH2.2 R21_IO_CH2.2 TP5_IO_CH2.1 U5_IO_CH2.6
NetC4_IO_CH2_2: C4_IO_CH2.2 JP2_IO_CH2.2 JP3_IO_CH2.2 R12_IO_CH2.2 U5_IO_CH2.2
NetC4_OI_CH1_1: C4_OI_CH1.1 R12_OI_CH1.1 R15_OI_CH1.2 R21_OI_CH1.2 TP5_OI_CH1.1 U5_OI_CH1.6 | length 535.1
  Component Side w15: R12_OI_CH1.1@6164.37,6240 6145,6220.63 6145,6187.31 6144.76,6187.31 6135.68,6178.23 6135.68,6070.68 6146.36,6060 U5_OI_CH1.6@6194.49,6060 6230,6060 6265,6025 6300,6025 6300.63,6025.63 R15_OI_CH1.2@6300.63,6110 ; C4_OI_CH1.1@6164.37,6325 6164.37,6240.63 R12_OI_CH1.1@6165,6240
NetC4_OI_CH1_2: C4_OI_CH1.2 JP2_OI_CH1.2 JP3_OI_CH1.2 R12_OI_CH1.2 U5_OI_CH1.2 | length 989.7
  Component Side w15: JP3_OI_CH1.2@5716.54,5865 5783.04,5931.5 5783.04,5996.42 5861.12,6074.5 5920.96,6074.5 5930.04,6083.58 5930.04,6085.04 5955,6110 ; JP2_OI_CH1.2@5716.54,6215 5861.46,6215 5930.04,6146.42 5930.04,6134.96 5955,6110 ; U5_OI_CH1.2@6005,6110 5955,6110 ; U5_OI_CH1.2@6005.51,6110 6055,6110 6085,6140 R12_OI_CH1.2@6085,6235 ; C4_OI_CH1.2@6085,6325 6085.63,6324.37 R12_OI_CH1.2@6085.63,6240
NetC4_OI_CH2_1: C4_OI_CH2.1 R12_OI_CH2.1 R15_OI_CH2.2 R21_OI_CH2.2 TP5_OI_CH2.1 U5_OI_CH2.6
NetC4_OI_CH2_2: C4_OI_CH2.2 JP2_OI_CH2.2 JP3_OI_CH2.2 R12_OI_CH2.2 U5_OI_CH2.2
NetC4_OI_CH3_1: C4_OI_CH3.1 R12_OI_CH3.1 R15_OI_CH3.2 R21_OI_CH3.2 TP5_OI_CH3.1 U5_OI_CH3.6
NetC4_OI_CH3_2: C4_OI_CH3.2 JP2_OI_CH3.2 JP3_OI_CH3.2 R12_OI_CH3.2 U5_OI_CH3.2
NetC4_OI_CH4_1: C4_OI_CH4.1 R12_OI_CH4.1 R15_OI_CH4.2 R21_OI_CH4.2 TP5_OI_CH4.1 U5_OI_CH4.6
NetC4_OI_CH4_2: C4_OI_CH4.2 JP2_OI_CH4.2 JP3_OI_CH4.2 R12_OI_CH4.2 U5_OI_CH4.2
NetD1_IO_CH1_2: D1_IO_CH1.2 R5_IO_CH1.2 U3_IO_CH1.2
NetD1_IO_CH2_2: D1_IO_CH2.2 R5_IO_CH2.2 U3_IO_CH2.2
NetD1_OI_CH1_2: D1_OI_CH1.2 R5_OI_CH1.2 U3_OI_CH1.2
NetD1_OI_CH2_2: D1_OI_CH2.2 R5_OI_CH2.2 U3_OI_CH2.2
NetD1_OI_CH3_2: D1_OI_CH3.2 R5_OI_CH3.2 U3_OI_CH3.2
NetD1_OI_CH4_2: D1_OI_CH4.2 R5_OI_CH4.2 U3_OI_CH4.2
NetIN_IO_CH1_1: IN_IO_CH1.1 R20_IO_CH1.2
NetIN_IO_CH2_1: IN_IO_CH2.1 R20_IO_CH2.2
NetIN_OI_CH1_1: IN_OI_CH1.1 R20_OI_CH1.2
NetIN_OI_CH2_1: IN_OI_CH2.1 R20_OI_CH2.2
NetIN_OI_CH3_1: IN_OI_CH3.1 R20_OI_CH3.2
NetIN_OI_CH4_1: IN_OI_CH4.1 R20_OI_CH4.2
NetJP1_IO_CH1_1: JP1_IO_CH1.1 R3_IO_CH1.1 | length 429.9
  Component Side w20: R3_IO_CH1.1@2166.54,4570 2206.54,4570 2335.54,4441 2367.08,4441 2443.08,4365 JP1_IO_CH1.1@2511.54,4365
NetJP1_IO_CH1_3: JP1_IO_CH1.3 R6_IO_CH1.1 | length 209.4
  Component Side w20: R6_IO_CH1.1@2166.54,4485 2166.54,4460 2261.54,4365 JP1_IO_CH1.3@2311.54,4365
NetJP1_IO_CH2_1: JP1_IO_CH2.1 R3_IO_CH2.1 | length 429.9
  Component Side w20: R3_IO_CH2.1@2166.54,1900 2206.54,1900 2335.54,1771 2367.08,1771 2443.08,1695 JP1_IO_CH2.1@2511.54,1695
NetJP1_IO_CH2_3: JP1_IO_CH2.3 R6_IO_CH2.1 | length 209.4
  Component Side w20: R6_IO_CH2.1@2166.54,1815 2166.54,1790 2261.54,1695 JP1_IO_CH2.3@2311.54,1695
NetJP1_OI_CH1_1: JP1_OI_CH1.1 R3_OI_CH1.1 | length 429.9
  Component Side w15: R3_OI_CH1.1@2166.54,6000 2206.54,6000 2335.54,5871 2367.08,5871 2443.08,5795 JP1_OI_CH1.1@2511.54,5795
NetJP1_OI_CH1_3: JP1_OI_CH1.3 R6_OI_CH1.1 | length 209.4
  Component Side w15: R6_OI_CH1.1@2166.54,5915 2166.54,5890 2261.54,5795 JP1_OI_CH1.3@2311.54,5795
NetJP1_OI_CH2_1: JP1_OI_CH2.1 R3_OI_CH2.1 | length 429.9
  Component Side w20: R3_OI_CH2.1@2166.54,5285 2206.54,5285 2335.54,5156 2367.08,5156 2443.08,5080 JP1_OI_CH2.1@2511.54,5080
NetJP1_OI_CH2_3: JP1_OI_CH2.3 R6_OI_CH2.1 | length 209.4
  Component Side w20: R6_OI_CH2.1@2166.54,5200 2166.54,5175 2261.54,5080 JP1_OI_CH2.3@2311.54,5080
NetJP1_OI_CH3_1: JP1_OI_CH3.1 R3_OI_CH3.1 | length 429.9
  Component Side w20: R3_OI_CH3.1@2167.17,3330 2207.17,3330 2336.17,3201 2367.71,3201 2443.71,3125 JP1_OI_CH3.1@2512.17,3125
NetJP1_OI_CH3_3: JP1_OI_CH3.3 R6_OI_CH3.1 | length 209.4
  Component Side w20: R6_OI_CH3.1@2167.17,3245 2167.17,3220 2262.17,3125 JP1_OI_CH3.3@2312.17,3125
NetJP1_OI_CH4_1: JP1_OI_CH4.1 R3_OI_CH4.1 | length 429.9
  Component Side w20: R3_OI_CH4.1@2166.54,2615 2206.54,2615 2335.54,2486 2367.08,2486 2443.08,2410 JP1_OI_CH4.1@2511.54,2410
NetJP1_OI_CH4_3: JP1_OI_CH4.3 R6_OI_CH4.1 | length 209.4
  Component Side w20: R6_OI_CH4.1@2166.54,2530 2166.54,2505 2261.54,2410 JP1_OI_CH4.3@2311.54,2410
NetJP2_IO_CH1_1: JP2_IO_CH1.1 R9_IO_CH1.1 R9_IO_CH1.2 | length 522.7
  Component Side w20: R9_IO_CH1.2@5466.54,4697.83 5466.54,4780 R9_IO_CH1.1@5566.54,4880 ; R9_IO_CH1.1@5566.54,4875 5851.54,4875 JP2_IO_CH1.1@5861.54,4885
NetJP2_IO_CH1_3: JP2_IO_CH1.3 R13_IO_CH1.1 R13_IO_CH1.2 | length 584.9
  Component Side w20: R13_IO_CH1.2@5466.54,4347.83 5466.54,4425 R13_IO_CH1.1@5566.54,4525 5601.54,4525 5761.54,4685 JP2_IO_CH1.3@5856.54,4685 JP2_IO_CH1.3@5866.54,4685
NetJP2_IO_CH2_1: JP2_IO_CH2.1 R9_IO_CH2.1 R9_IO_CH2.2 | length 522.7
  Component Side w20: R9_IO_CH2.2@5466.54,2027.83 5466.54,2110 R9_IO_CH2.1@5566.54,2210 ; R9_IO_CH2.1@5566.54,2205 5851.54,2205 JP2_IO_CH2.1@5861.54,2215
NetJP2_IO_CH2_3: JP2_IO_CH2.3 R13_IO_CH2.1 R13_IO_CH2.2 | length 584.9
  Component Side w20: R13_IO_CH2.2@5466.54,1677.83 5466.54,1755 R13_IO_CH2.1@5566.54,1855 5601.54,1855 5761.54,2015 JP2_IO_CH2.3@5856.54,2015 JP2_IO_CH2.3@5866.54,2015
NetJP2_OI_CH1_1: JP2_OI_CH1.1 R9_OI_CH1.1 R9_OI_CH1.2 | length 522.7
  Component Side w15: R9_OI_CH1.2@5466.54,6127.83 5466.54,6210 R9_OI_CH1.1@5566.54,6310 ; R9_OI_CH1.1@5566.54,6305 5851.54,6305 JP2_OI_CH1.1@5861.54,6315
NetJP2_OI_CH1_3: JP2_OI_CH1.3 R13_OI_CH1.1 R13_OI_CH1.2 | length 584.9
  Component Side w15: R13_OI_CH1.2@5466.54,5777.83 5466.54,5855 5566.54,5955 5601.54,5955 5761.54,6115 JP2_OI_CH1.3@5856.54,6115 JP2_OI_CH1.3@5866.54,6115
NetJP2_OI_CH2_1: JP2_OI_CH2.1 R9_OI_CH2.1 R9_OI_CH2.2 | length 522.7
  Component Side w20: R9_OI_CH2.2@5466.54,5412.83 5466.54,5495 R9_OI_CH2.1@5566.54,5595 ; R9_OI_CH2.1@5566.54,5590 5851.54,5590 JP2_OI_CH2.1@5861.54,5600
NetJP2_OI_CH2_3: JP2_OI_CH2.3 R13_OI_CH2.1 R13_OI_CH2.2 | length 584.9
  Component Side w20: R13_OI_CH2.2@5466.54,5062.83 5466.54,5140 R13_OI_CH2.1@5566.54,5240 5601.54,5240 5761.54,5400 JP2_OI_CH2.3@5856.54,5400 JP2_OI_CH2.3@5866.54,5400
NetJP2_OI_CH3_1: JP2_OI_CH3.1 R9_OI_CH3.1 R9_OI_CH3.2 | length 522.7
  Component Side w20: R9_OI_CH3.2@5467.17,3457.83 5467.17,3540 R9_OI_CH3.1@5567.17,3640 ; R9_OI_CH3.1@5567.17,3635 5852.17,3635 JP2_OI_CH3.1@5862.17,3645
NetJP2_OI_CH3_3: JP2_OI_CH3.3 R13_OI_CH3.1 R13_OI_CH3.2 | length 584.9
  Component Side w20: R13_OI_CH3.2@5467.17,3107.83 5467.17,3185 R13_OI_CH3.1@5567.17,3285 5602.17,3285 5762.17,3445 JP2_OI_CH3.3@5857.17,3445 JP2_OI_CH3.3@5867.17,3445
NetJP2_OI_CH4_1: JP2_OI_CH4.1 R9_OI_CH4.1 R9_OI_CH4.2 | length 522.7
  Component Side w20: R9_OI_CH4.2@5466.54,2742.83 5466.54,2825 R9_OI_CH4.1@5566.54,2925 ; R9_OI_CH4.1@5566.54,2920 5851.54,2920 JP2_OI_CH4.1@5861.54,2930
NetJP2_OI_CH4_3: JP2_OI_CH4.3 R13_OI_CH4.1 R13_OI_CH4.2 | length 584.9
  Component Side w20: R13_OI_CH4.2@5466.54,2392.83 5466.54,2470 R13_OI_CH4.1@5566.54,2570 5601.54,2570 5761.54,2730 JP2_OI_CH4.3@5856.54,2730 JP2_OI_CH4.3@5866.54,2730
NetJP3_IO_CH1_1: JP3_IO_CH1.1 R16_IO_CH1.1 R16_IO_CH1.2 | length 1195
  Component Side w20: R16_IO_CH1.1@5161.54,4525 5061.54,4425 R16_IO_CH1.2@5061.54,4347.83 5362.34,4347.83 5439.4,4270.78 5493.68,4270.78 5614.9,4392 5781.99,4392 5856.54,4466.54 JP3_IO_CH1.1@5856.54,4535
NetJP3_IO_CH1_3: JP3_IO_CH1.3 R18_IO_CH1.1 R18_IO_CH1.2 | length 924.7
  Component Side w20: 5034.4,4270.78 5023.85,4281.32 5023.85,4426.91 5061.54,4464.6 R18_IO_CH1.2@5061.54,4697.83 ; R18_IO_CH1.2@5061.54,4702.83 5061.54,4780 R18_IO_CH1.1@5161.54,4880 ; 5597.5,4335 JP3_IO_CH1.3@5856.54,4335
NetJP3_IO_CH2_1: JP3_IO_CH2.1 R16_IO_CH2.1 R16_IO_CH2.2 | length 1195
  Component Side w20: R16_IO_CH2.1@5161.54,1855 5061.54,1755 R16_IO_CH2.2@5061.54,1677.83 5362.34,1677.83 5439.4,1600.78 5493.68,1600.78 5614.9,1722 5781.99,1722 5856.54,1796.54 JP3_IO_CH2.1@5856.54,1865
NetJP3_IO_CH2_3: JP3_IO_CH2.3 R18_IO_CH2.1 R18_IO_CH2.2 | length 924.7
  Component Side w20: 5034.4,1600.78 5023.85,1611.32 5023.85,1756.91 5061.54,1794.6 R18_IO_CH2.2@5061.54,2027.83 ; R18_IO_CH2.2@5061.54,2032.83 5061.54,2110 R18_IO_CH2.1@5161.54,2210 ; 5597.5,1665 JP3_IO_CH2.3@5856.54,1665
NetJP3_OI_CH1_1: JP3_OI_CH1.1 R16_OI_CH1.1 R16_OI_CH1.2 | length 1189.7
  Component Side w15: R16_OI_CH1.2@5060,5782.83 R16_OI_CH1.2@5061.54,5782.83 ; R16_OI_CH1.2@5061.54,5777.83 R16_OI_CH1.2@5061.54,5782.83 ; R16_OI_CH1.1@5161.54,5955 5061.54,5855 R16_OI_CH1.2@5061.54,5782.83 ; JP3_OI_CH1.1@5855,5965 5855,5898.54 5780.96,5824.5 5612.33,5824.5 5496.11,5708.28 5443.89,5708.28 5369.34,5782.83 R16_OI_CH1.2@5061.54,5782.83
NetJP3_OI_CH1_3: JP3_OI_CH1.3 R18_OI_CH1.1 R18_OI_CH1.2 | length 1520.3
  Component Side w15: R18_OI_CH1.2@5060,6125 5060,5910 5024.81,5874.81 5024.81,5717.36 5033.89,5708.28 5086.11,5708.28 5087.83,5710 5409.65,5710 5434.37,5685.28 5505.63,5685.28 5585.35,5765 JP3_OI_CH1.3@5856.54,5765 ; R18_OI_CH1.2@5061.54,6132.83 5061.54,6210 R18_OI_CH1.1@5161.54,6310
NetJP3_OI_CH2_1: JP3_OI_CH2.1 R16_OI_CH2.1 R16_OI_CH2.2 | length 1195
  Component Side w20: R16_OI_CH2.1@5161.54,5240 5061.54,5140 R16_OI_CH2.2@5061.54,5062.83 5362.34,5062.83 5439.4,4985.78 5493.68,4985.78 5614.9,5107 5781.99,5107 5856.54,5181.54 JP3_OI_CH2.1@5856.54,5250
NetJP3_OI_CH2_3: JP3_OI_CH2.3 R18_OI_CH2.1 R18_OI_CH2.2 | length 924.7
  Component Side w20: 5034.4,4985.78 5023.85,4996.32 5023.85,5141.91 5061.54,5179.6 R18_OI_CH2.2@5061.54,5412.83 ; R18_OI_CH2.2@5061.54,5417.83 5061.54,5495 R18_OI_CH2.1@5161.54,5595 ; 5597.5,5050 JP3_OI_CH2.3@5856.54,5050
NetJP3_OI_CH3_1: JP3_OI_CH3.1 R16_OI_CH3.1 R16_OI_CH3.2 | length 1195
  Component Side w20: R16_OI_CH3.1@5162.17,3285 5062.17,3185 R16_OI_CH3.2@5062.17,3107.83 5362.97,3107.83 5440.03,3030.78 5494.31,3030.78 5615.53,3152 5782.62,3152 5857.17,3226.54 JP3_OI_CH3.1@5857.17,3295
NetJP3_OI_CH3_3: JP3_OI_CH3.3 R18_OI_CH3.1 R18_OI_CH3.2 | length 924.7
  Component Side w20: 5035.03,3030.78 5024.48,3041.32 5024.48,3186.91 5062.17,3224.6 R18_OI_CH3.2@5062.17,3457.83 ; R18_OI_CH3.2@5062.17,3462.83 5062.17,3540 R18_OI_CH3.1@5162.17,3640 ; 5598.13,3095 JP3_OI_CH3.3@5857.17,3095
NetJP3_OI_CH4_1: JP3_OI_CH4.1 R16_OI_CH4.1 R16_OI_CH4.2 | length 1195
  Component Side w20: R16_OI_CH4.1@5161.54,2570 5061.54,2470 R16_OI_CH4.2@5061.54,2392.83 5362.34,2392.83 5439.4,2315.78 5493.68,2315.78 5614.9,2437 5781.99,2437 5856.54,2511.54 JP3_OI_CH4.1@5856.54,2580
NetJP3_OI_CH4_3: JP3_OI_CH4.3 R18_OI_CH4.1 R18_OI_CH4.2 | length 924.7
  Component Side w20: 5034.4,2315.78 5023.85,2326.32 5023.85,2471.91 5061.54,2509.6 R18_OI_CH4.2@5061.54,2742.83 ; R18_OI_CH4.2@5061.54,2747.83 5061.54,2825 R18_OI_CH4.1@5161.54,2925 ; 5597.5,2380 JP3_OI_CH4.3@5856.54,2380
NetOUT_IO_CH1_1: OUT_IO_CH1.1 R21_IO_CH1.1
NetOUT_IO_CH2_1: OUT_IO_CH2.1 R21_IO_CH2.1
NetOUT_OI_CH1_1: OUT_OI_CH1.1 R21_OI_CH1.1 | length 325.5
  Component Side w15: OUT_OI_CH1.1@6190,5825 6233.16,5868.16 6313.54,5868.16 6379.37,5933.99 R21_OI_CH1.1@6379.37,6025
NetOUT_OI_CH2_1: OUT_OI_CH2.1 R21_OI_CH2.1
NetOUT_OI_CH3_1: OUT_OI_CH3.1 R21_OI_CH3.1
NetOUT_OI_CH4_1: OUT_OI_CH4.1 R21_OI_CH4.1
NetR3_IO_CH1_2: R3_IO_CH1.2 R6_IO_CH1.2 TP2_IO_CH1.1 U1_IO_CH1.1 U1_IO_CH1.2 | length 439.2
  Component Side w20: U1_IO_CH1.2@2031.54,4745 2032.05,4745.51 U1_IO_CH1.1@2032.05,4795 2091.54,4795 2101.54,4785 2101.54,4620 2086.54,4605 R3_IO_CH1.2@2086.54,4570 ; R6_IO_CH1.2@2086.54,4485 2087.17,4485.63 R3_IO_CH1.2@2087.17,4570 ; R3_IO_CH1.2@2093.36,4570 2091.54,4570 R3_IO_CH1.2@2096.54,4565
NetR3_IO_CH2_2: R3_IO_CH2.2 R6_IO_CH2.2 TP2_IO_CH2.1 U1_IO_CH2.1 U1_IO_CH2.2 | length 439.2
  Component Side w20: U1_IO_CH2.2@2031.54,2075 2032.05,2075.51 U1_IO_CH2.1@2032.05,2125 2091.54,2125 2101.54,2115 2101.54,1950 2086.54,1935 R3_IO_CH2.2@2086.54,1900 ; R6_IO_CH2.2@2086.54,1815 2087.17,1815.63 R3_IO_CH2.2@2087.17,1900 ; R3_IO_CH2.2@2093.36,1900 2091.54,1900 R3_IO_CH2.2@2096.54,1895
NetR3_OI_CH1_2: R3_OI_CH1.2 R6_OI_CH1.2 TP2_OI_CH1.1 U1_OI_CH1.1 U1_OI_CH1.2 | length 439.2
  Component Side w15: U1_OI_CH1.2@2031.54,6175 2032.05,6175.51 U1_OI_CH1.1@2032.05,6225 2091.54,6225 2101.54,6215 2101.54,6050 2086.54,6035 R3_OI_CH1.2@2086.54,6000 ; R6_OI_CH1.2@2086.54,5915 2087.17,5915.63 R3_OI_CH1.2@2087.17,6000 ; R3_OI_CH1.2@2093.36,6000 2091.54,6000 R3_OI_CH1.2@2096.54,5995
NetR3_OI_CH2_2: R3_OI_CH2.2 R6_OI_CH2.2 TP2_OI_CH2.1 U1_OI_CH2.1 U1_OI_CH2.2 | length 439.2
  Component Side w20: U1_OI_CH2.2@2031.54,5460 2032.05,5460.51 U1_OI_CH2.1@2032.05,5510 2091.54,5510 2101.54,5500 2101.54,5335 2086.54,5320 R3_OI_CH2.2@2086.54,5285 ; R6_OI_CH2.2@2086.54,5200 2087.17,5200.63 R3_OI_CH2.2@2087.17,5285 ; R3_OI_CH2.2@2093.36,5285 2091.54,5285 R3_OI_CH2.2@2096.54,5280
NetR3_OI_CH3_2: R3_OI_CH3.2 R6_OI_CH3.2 TP2_OI_CH3.1 U1_OI_CH3.1 U1_OI_CH3.2 | length 439.2
  Component Side w20: U1_OI_CH3.2@2032.17,3505 2032.68,3505.51 U1_OI_CH3.1@2032.68,3555 2092.17,3555 2102.17,3545 2102.17,3380 2087.17,3365 R3_OI_CH3.2@2087.17,3330 ; R6_OI_CH3.2@2087.17,3245 2087.8,3245.63 R3_OI_CH3.2@2087.8,3330 ; R3_OI_CH3.2@2093.99,3330 2092.17,3330 R3_OI_CH3.2@2097.17,3325
NetR3_OI_CH4_2: R3_OI_CH4.2 R6_OI_CH4.2 TP2_OI_CH4.1 U1_OI_CH4.1 U1_OI_CH4.2 | length 439.2
  Component Side w20: U1_OI_CH4.2@2031.54,2790 2032.05,2790.51 U1_OI_CH4.1@2032.05,2840 2091.54,2840 2101.54,2830 2101.54,2665 2086.54,2650 R3_OI_CH4.2@2086.54,2615 ; R6_OI_CH4.2@2086.54,2530 2087.17,2530.63 R3_OI_CH4.2@2087.17,2615 ; R3_OI_CH4.2@2093.36,2615 2091.54,2615 R3_OI_CH4.2@2096.54,2610
NetR7_IO_CH1_2: R7_IO_CH1.2 R19_IO_CH1.1 R20_IO_CH1.1 TP1_IO_CH1.1 U1_IO_CH1.3
NetR7_IO_CH2_2: R7_IO_CH2.2 R19_IO_CH2.1 R20_IO_CH2.1 TP1_IO_CH2.1 U1_IO_CH2.3
NetR7_OI_CH1_2: R7_OI_CH1.2 R19_OI_CH1.1 R20_OI_CH1.1 TP1_OI_CH1.1 U1_OI_CH1.3
NetR7_OI_CH2_2: R7_OI_CH2.2 R19_OI_CH2.1 R20_OI_CH2.1 TP1_OI_CH2.1 U1_OI_CH2.3
NetR7_OI_CH3_2: R7_OI_CH3.2 R19_OI_CH3.1 R20_OI_CH3.1 TP1_OI_CH3.1 U1_OI_CH3.3
NetR7_OI_CH4_2: R7_OI_CH4.2 R19_OI_CH4.1 R20_OI_CH4.1 TP1_OI_CH4.1 U1_OI_CH4.3
NetR8_IO_CH1_1: R8_IO_CH1.1 R9_IO_CH1.3
NetR8_IO_CH2_1: R8_IO_CH2.1 R9_IO_CH2.3
NetR8_OI_CH1_1: R8_OI_CH1.1 R9_OI_CH1.3 | length 126
  Component Side w15: R8_OI_CH1.1@5261.54,6250.63 5310.63,6250.63 R9_OI_CH1.3@5365,6305
NetR8_OI_CH2_1: R8_OI_CH2.1 R9_OI_CH2.3
NetR8_OI_CH3_1: R8_OI_CH3.1 R9_OI_CH3.3
NetR8_OI_CH4_1: R8_OI_CH4.1 R9_OI_CH4.3
NetR11_IO_CH1_1: R11_IO_CH1.1 R13_IO_CH1.3 | length 121.3
  Component Side w20: R11_IO_CH1.1@5261.54,4490.63 5327.17,4490.63 R13_IO_CH1.3@5366.54,4530
NetR11_IO_CH2_1: R11_IO_CH2.1 R13_IO_CH2.3 | length 121.3
  Component Side w20: R11_IO_CH2.1@5261.54,1820.63 5327.17,1820.63 R13_IO_CH2.3@5366.54,1860
NetR11_OI_CH1_1: R11_OI_CH1.1 R13_OI_CH1.3 | length 121.3
  Component Side w15: R11_OI_CH1.1@5261.54,5920.63 5327.17,5920.63 R13_OI_CH1.3@5366.54,5960
NetR11_OI_CH2_1: R11_OI_CH2.1 R13_OI_CH2.3 | length 121.3
  Component Side w20: R11_OI_CH2.1@5261.54,5205.63 5327.17,5205.63 R13_OI_CH2.3@5366.54,5245
NetR11_OI_CH3_1: R11_OI_CH3.1 R13_OI_CH3.3 | length 121.3
  Component Side w20: R11_OI_CH3.1@5262.17,3250.63 5327.8,3250.63 R13_OI_CH3.3@5367.17,3290
NetR11_OI_CH4_1: R11_OI_CH4.1 R13_OI_CH4.3 | length 121.3
  Component Side w20: R11_OI_CH4.1@5261.54,2535.63 5327.17,2535.63 R13_OI_CH4.3@5366.54,2575
NetR14_IO_CH1_1: R14_IO_CH1.1 R16_IO_CH1.3 | length 112.4
  Component Side w20: R14_IO_CH1.1@4861.54,4495 4921.54,4495 4951.54,4525 R16_IO_CH1.3@4961.54,4525
NetR14_IO_CH2_1: R14_IO_CH2.1 R16_IO_CH2.3 | length 112.4
  Component Side w20: R14_IO_CH2.1@4861.54,1825 4921.54,1825 4951.54,1855 R16_IO_CH2.3@4961.54,1855
NetR14_OI_CH1_1: R14_OI_CH1.1 R16_OI_CH1.3 | length 112.4
  Component Side w15: R14_OI_CH1.1@4861.54,5925 4921.54,5925 4951.54,5955 R16_OI_CH1.3@4961.54,5955
NetR14_OI_CH2_1: R14_OI_CH2.1 R16_OI_CH2.3 | length 112.4
  Component Side w20: R14_OI_CH2.1@4861.54,5210 4921.54,5210 4951.54,5240 R16_OI_CH2.3@4961.54,5240
NetR14_OI_CH3_1: R14_OI_CH3.1 R16_OI_CH3.3 | length 112.4
  Component Side w20: R14_OI_CH3.1@4862.17,3255 4922.17,3255 4952.17,3285 R16_OI_CH3.3@4962.17,3285
NetR14_OI_CH4_1: R14_OI_CH4.1 R16_OI_CH4.3 | length 112.4
  Component Side w20: R14_OI_CH4.1@4861.54,2540 4921.54,2540 4951.54,2570 R16_OI_CH4.3@4961.54,2570
NetR17_IO_CH1_1: R17_IO_CH1.1 R18_IO_CH1.3 | length 102.7
  Component Side w20: R17_IO_CH1.1@4861.54,4899.37 4957.17,4899.37 R18_IO_CH1.3@4961.54,4895 ; R18_IO_CH1.3@4960.91,4909.37 R18_IO_CH1.3@4961.54,4910
NetR17_IO_CH2_1: R17_IO_CH2.1 R18_IO_CH2.3 | length 102.7
  Component Side w20: R17_IO_CH2.1@4861.54,2229.37 4957.17,2229.37 R18_IO_CH2.3@4961.54,2225 ; R18_IO_CH2.3@4960.91,2239.37 R18_IO_CH2.3@4961.54,2240
NetR17_OI_CH1_1: R17_OI_CH1.1 R18_OI_CH1.3 | length 102.7
  Component Side w15: R17_OI_CH1.1@4861.54,6329.37 4957.17,6329.37 R18_OI_CH1.3@4961.54,6325 ; R18_OI_CH1.3@4960.91,6339.37 R18_OI_CH1.3@4961.54,6340
NetR17_OI_CH2_1: R17_OI_CH2.1 R18_OI_CH2.3 | length 102.7
  Component Side w20: R17_OI_CH2.1@4861.54,5614.37 4957.17,5614.37 R18_OI_CH2.3@4961.54,5610 ; R18_OI_CH2.3@4960.91,5624.37 R18_OI_CH2.3@4961.54,5625
NetR17_OI_CH3_1: R17_OI_CH3.1 R18_OI_CH3.3 | length 102.7
  Component Side w20: R17_OI_CH3.1@4862.17,3659.37 4957.8,3659.37 R18_OI_CH3.3@4962.17,3655 ; R18_OI_CH3.3@4961.54,3669.37 R18_OI_CH3.3@4962.17,3670
NetR17_OI_CH4_1: R17_OI_CH4.1 R18_OI_CH4.3 | length 102.7
  Component Side w20: R17_OI_CH4.1@4861.54,2944.37 4957.17,2944.37 R18_OI_CH4.3@4961.54,2940 ; R18_OI_CH4.3@4960.91,2954.37 R18_OI_CH4.3@4961.54,2955
PA1: PA.1 R15_OI_CH1.1
PA2: PA.2 R15_OI_CH2.1
PA3: PA.3 R19_IO_CH1.2
PA4: PA.4 R15_OI_CH3.1
PA5: PA.5 R15_OI_CH4.1
PA6: PA.6 R19_IO_CH2.2
PB1: PB.1 R19_OI_CH1.2
PB2: PB.2 R19_OI_CH2.2
PB3: PB.3 R15_IO_CH1.1
PB4: PB.4 R19_OI_CH3.2
PB5: PB.5 R19_OI_CH4.2
PB6: PB.6 R15_IO_CH2.1
V+OUT_IO_CH1: C8_IO_CH1.2 C9_IO_CH1.2 C11_IO_CH1.1 U4_IO_CH1.7 U5_IO_CH1.7
V-OUT_IO_CH1: C13_IO_CH1.2 C16_IO_CH1.2 C17_IO_CH1.2 U4_IO_CH1.4 U5_IO_CH1.4
pads on no net: "U6_Side A power supply and references.1" "U6_Side A power supply and references.3" "U6_Side A power supply and references.5" "U6_Side A power supply and references.7" "U6_Side A power supply and references.8" "U6_Side B power supply and references.1" "U6_Side B power supply and references.3" "U6_Side B power supply and references.5" "U6_Side B power supply and references.7" "U6_Side B power supply and references.8" U2_IO_CH1.1 U2_IO_CH1.5 U2_IO_CH1.8 U2_IO_CH2.1 U2_IO_CH2.5 U2_IO_CH2.8 U2_OI_CH1.1 U2_OI_CH1.5 U2_OI_CH1.8 U2_OI_CH2.1 U2_OI_CH2.5 U2_OI_CH2.8 U2_OI_CH3.1 U2_OI_CH3.5 U2_OI_CH3.8 U2_OI_CH4.1 U2_OI_CH4.5 U2_OI_CH4.8 U3_IO_CH1.7 U3_IO_CH1.8 U3_IO_CH2.7 U3_IO_CH2.8 U3_OI_CH1.7 U3_OI_CH1.8 U3_OI_CH2.7 U3_OI_CH2.8 U3_OI_CH3.7 U3_OI_CH3.8 U3_OI_CH4.7 U3_OI_CH4.8 U4_IO_CH1.1 U4_IO_CH1.5 U4_IO_CH1.8 U4_IO_CH2.1 U4_IO_CH2.5 U4_IO_CH2.8 U4_OI_CH1.1 U4_OI_CH1.5 U4_OI_CH1.8 U4_OI_CH2.1 U4_OI_CH2.5 U4_OI_CH2.8 U4_OI_CH3.1 U4_OI_CH3.5 U4_OI_CH3.8 U4_OI_CH4.1 U4_OI_CH4.5 U4_OI_CH4.8 U5_IO_CH1.1 U5_IO_CH1.5 U5_IO_CH1.8 U5_IO_CH2.1 U5_IO_CH2.5 U5_IO_CH2.8 U5_OI_CH1.1 U5_OI_CH1.5 U5_OI_CH1.8 U5_OI_CH2.1 U5_OI_CH2.5 U5_OI_CH2.8 U5_OI_CH3.1 U5_OI_CH3.5 U5_OI_CH3.8 U5_OI_CH4.1 U5_OI_CH4.5 U5_OI_CH4.8

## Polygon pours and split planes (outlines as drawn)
COMA on Ground "COMA_L04_P000" (solid, pour order 0): 3750,1010 3750,6960 1010,6960 1010,1010
COMB on Ground "COMB_L04_P002" (solid, pour order 2): 4000,1010 4000,6960 6730,6960 6730,1010
+15B on V+ "+15B_L02_P006" (solid, pour order 6): 4000,1010 4000,6960 6730,6960 6730,1010
+15A on V+ "+15A_L02_P004" (solid, pour order 4): 3750,1010 3750,6960 1010,6960 1010,1010
-15B on V- "-15B_L03_P007" (solid, pour order 7): 4000,1010 4000,6960 6730,6960 6730,1010
-15A on V- "-15A_L03_P005" (solid, pour order 5): 3750,1010 3750,6960 1010,6960 1010,1010

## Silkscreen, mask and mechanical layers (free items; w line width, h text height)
Mechanical 1:
  the board outline again, w2
Mechanical 13:
  lines w2: 1030,1570 3560,1570 ; 1030,6400 3560,6400 ; 1270,1265 1270,6695 ; 3320,1265 3320,6695 ; 4180,1570 6710,1570 ; 4180,6400 6710,6400 ; 4420,1265 4420,6695 ; 6470,1265 6470,6695 ; 7295,1575 9825,1575 ; 7295,6405 9825,6405 ; 7535,1270 7535,6700 ; 9585,1270 9585,6700 ; 1030,1030 1030,6940 3560,6940 3560,1030 1030,1030 ; 4180,1030 6710,1030 6710,6940 4180,6940 4180,1030 ; 7295,1035 7295,6945 9825,6945 9825,1035 7295,1035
